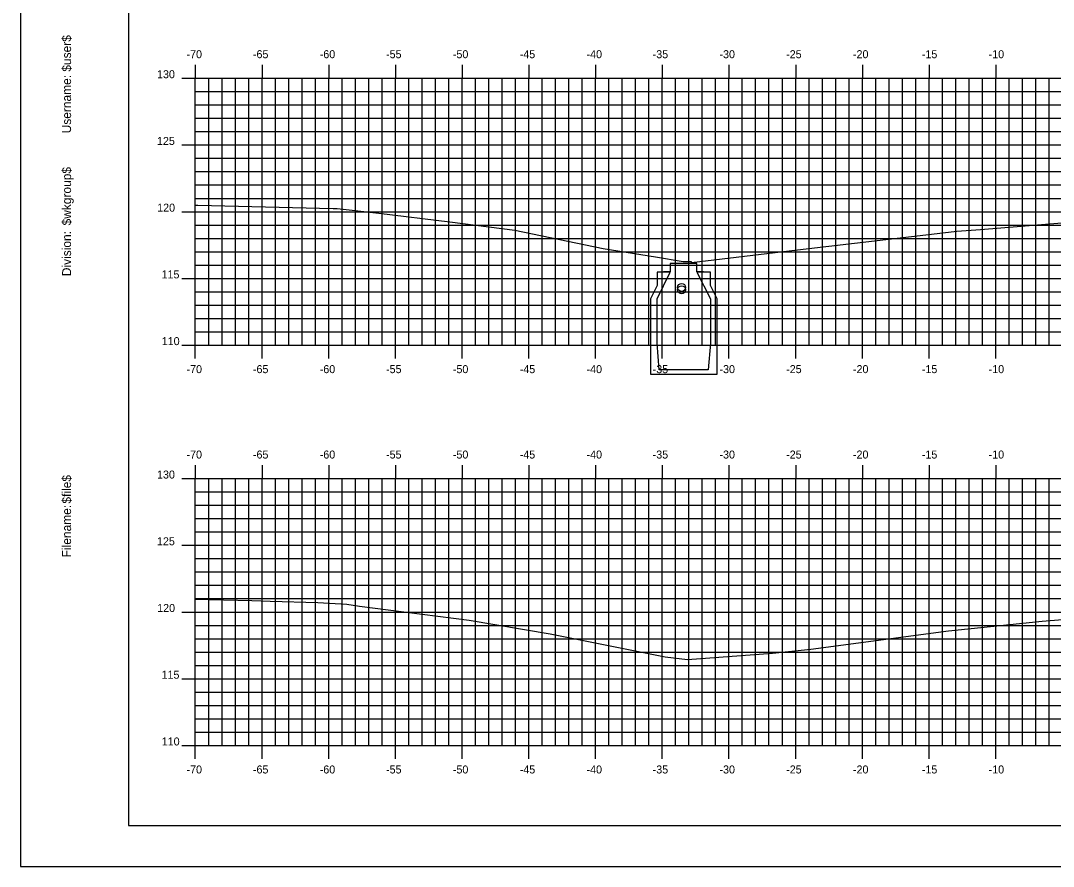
# Model space of a CAD drawing. Extents: x 853069 to 853241, y 365624 to 365734.
# Drawn here: x 853069 to 853146.4, y 365624 to 365687.3 of the extents above; entities that cross this region are included whole.
import ezdxf

# ---------------------------------------------------------------- set-up
doc = ezdxf.new("R2010")
doc.units = 0
for name, color, linetype in [('BORDER', 7, 'Continuous'), ('H_V ANNOTATION', 7, 'Continuous'), ('MAJOR', 7, 'Continuous'), ('MINOR', 7, 'Continuous'), ('PLOT BOUNDARY', 7, 'Continuous'), ('S_Drainage_CB', 7, 'Continuous'), ('S_Drainage_Invert', 7, 'Continuous'), ('S_Roadway_Centerline', 7, 'Continuous')]:
    doc.layers.add(name, color=color, linetype=linetype)

msp = doc.modelspace()

# ---------------------------------------------------------------- linework, layer by layer
at = {"layer": 'BORDER'}
msp.add_lwpolyline([(853077.062, 365627.027), (853237.062, 365627.027), (853237.062, 365732.027), (853077.062, 365732.027)], close=True, dxfattribs=at)
at = {"layer": 'MAJOR'}
for p, q in [((853082.061, 365684.029), (853082.061, 365683.027)), ((853087.061, 365684.029), (853087.061, 365683.027)), ((853092.061, 365684.029), (853092.061, 365683.027)), ((853097.061, 365684.029), (853097.061, 365683.027)), ((853102.061, 365684.029), (853102.061, 365683.027)), ((853107.061, 365684.029), (853107.061, 365683.027)), ((853112.061, 365684.029), (853112.061, 365683.027)), ((853117.061, 365684.029), (853117.061, 365683.027)), ((853122.061, 365684.029), (853122.061, 365683.027)), ((853127.061, 365684.029), (853127.061, 365683.027)), ((853132.061, 365684.029), (853132.061, 365683.027)), ((853137.061, 365684.029), (853137.061, 365683.027)), ((853142.061, 365684.029), (853142.061, 365683.027)), ((853081.059, 365683.027), (853082.061, 365683.027)), ((853082.061, 365683.027), (853222.061, 365683.027)), ((853082.061, 365663.027), (853082.061, 365683.027)), ((853082.061, 365663.027), (853082.061, 365683.027)), ((853082.061, 365683.027), (853222.061, 365683.027)), ((853087.061, 365663.027), (853087.061, 365683.027)), ((853092.061, 365663.027), (853092.061, 365683.027)), ((853097.061, 365663.027), (853097.061, 365683.027)), ((853102.061, 365663.027), (853102.061, 365683.027)), ((853107.061, 365663.027), (853107.061, 365683.027)), ((853112.061, 365663.027), (853112.061, 365683.027)), ((853117.061, 365663.027), (853117.061, 365683.027)), ((853122.061, 365663.027), (853122.061, 365683.027)), ((853127.061, 365663.027), (853127.061, 365683.027)), ((853132.061, 365663.027), (853132.061, 365683.027)), ((853137.061, 365663.027), (853137.061, 365683.027)), ((853142.061, 365663.027), (853142.061, 365683.027)), ((853081.059, 365678.027), (853082.061, 365678.027)), ((853082.061, 365678.027), (853222.061, 365678.027)), ((853081.059, 365673.027), (853082.061, 365673.027)), ((853082.061, 365673.027), (853222.061, 365673.027)), ((853081.059, 365668.027), (853082.061, 365668.027)), ((853082.061, 365668.027), (853222.061, 365668.027)), ((853081.059, 365663.027), (853082.061, 365663.027)), ((853082.061, 365663.027), (853222.061, 365663.027)), ((853082.061, 365663.027), (853222.061, 365663.027)), ((853082.061, 365662.025), (853082.061, 365663.027)), ((853087.061, 365662.025), (853087.061, 365663.027)), ((853092.061, 365662.025), (853092.061, 365663.027)), ((853097.061, 365662.025), (853097.061, 365663.027)), ((853102.061, 365662.025), (853102.061, 365663.027)), ((853107.061, 365662.025), (853107.061, 365663.027)), ((853112.061, 365662.025), (853112.061, 365663.027)), ((853117.061, 365662.025), (853117.061, 365663.027)), ((853122.061, 365662.025), (853122.061, 365663.027)), ((853127.061, 365662.025), (853127.061, 365663.027)), ((853132.061, 365662.025), (853132.061, 365663.027)), ((853137.061, 365662.025), (853137.061, 365663.027)), ((853142.061, 365662.025), (853142.061, 365663.027)), ((853082.061, 365654.029), (853082.061, 365653.027)), ((853087.061, 365654.029), (853087.061, 365653.027)), ((853092.061, 365654.029), (853092.061, 365653.027)), ((853097.061, 365654.029), (853097.061, 365653.027)), ((853102.061, 365654.029), (853102.061, 365653.027)), ((853107.061, 365654.029), (853107.061, 365653.027)), ((853112.061, 365654.029), (853112.061, 365653.027)), ((853117.061, 365654.029), (853117.061, 365653.027)), ((853122.061, 365654.029), (853122.061, 365653.027)), ((853127.061, 365654.029), (853127.061, 365653.027)), ((853132.061, 365654.029), (853132.061, 365653.027)), ((853137.061, 365654.029), (853137.061, 365653.027)), ((853142.061, 365654.029), (853142.061, 365653.027)), ((853081.059, 365653.027), (853082.061, 365653.027)), ((853082.061, 365653.027), (853222.061, 365653.027)), ((853082.061, 365633.027), (853082.061, 365653.027)), ((853082.061, 365633.027), (853082.061, 365653.027)), ((853082.061, 365653.027), (853222.061, 365653.027)), ((853087.061, 365633.027), (853087.061, 365653.027)), ((853092.061, 365633.027), (853092.061, 365653.027)), ((853097.061, 365633.027), (853097.061, 365653.027)), ((853102.061, 365633.027), (853102.061, 365653.027)), ((853107.061, 365633.027), (853107.061, 365653.027)), ((853112.061, 365633.027), (853112.061, 365653.027)), ((853117.061, 365633.027), (853117.061, 365653.027)), ((853122.061, 365633.027), (853122.061, 365653.027)), ((853127.061, 365633.027), (853127.061, 365653.027)), ((853132.061, 365633.027), (853132.061, 365653.027)), ((853137.061, 365633.027), (853137.061, 365653.027)), ((853142.061, 365633.027), (853142.061, 365653.027)), ((853081.059, 365648.027), (853082.061, 365648.027)), ((853082.061, 365648.027), (853222.061, 365648.027)), ((853081.059, 365643.027), (853082.061, 365643.027)), ((853082.061, 365643.027), (853222.061, 365643.027)), ((853081.059, 365638.027), (853082.061, 365638.027)), ((853082.061, 365638.027), (853222.061, 365638.027)), ((853081.059, 365633.027), (853082.061, 365633.027)), ((853082.061, 365633.027), (853222.061, 365633.027)), ((853082.061, 365633.027), (853222.061, 365633.027)), ((853082.061, 365632.025), (853082.061, 365633.027)), ((853087.061, 365632.025), (853087.061, 365633.027)), ((853092.061, 365632.025), (853092.061, 365633.027)), ((853097.061, 365632.025), (853097.061, 365633.027)), ((853102.061, 365632.025), (853102.061, 365633.027)), ((853107.061, 365632.025), (853107.061, 365633.027)), ((853112.061, 365632.025), (853112.061, 365633.027)), ((853117.061, 365632.025), (853117.061, 365633.027)), ((853122.061, 365632.025), (853122.061, 365633.027)), ((853127.061, 365632.025), (853127.061, 365633.027)), ((853132.061, 365632.025), (853132.061, 365633.027)), ((853137.061, 365632.025), (853137.061, 365633.027)), ((853142.061, 365632.025), (853142.061, 365633.027))]:
    msp.add_line(p, q, dxfattribs=at)
at = {"layer": 'MINOR'}
for p, q in [((853083.061, 365663.027), (853083.061, 365683.027)), ((853084.061, 365663.027), (853084.061, 365683.027)), ((853085.061, 365663.027), (853085.061, 365683.027)), ((853086.061, 365663.027), (853086.061, 365683.027)), ((853088.061, 365663.027), (853088.061, 365683.027)), ((853089.061, 365663.027), (853089.061, 365683.027)), ((853090.061, 365663.027), (853090.061, 365683.027)), ((853091.061, 365663.027), (853091.061, 365683.027)), ((853093.061, 365663.027), (853093.061, 365683.027)), ((853094.061, 365663.027), (853094.061, 365683.027)), ((853095.061, 365663.027), (853095.061, 365683.027)), ((853096.061, 365663.027), (853096.061, 365683.027)), ((853098.061, 365663.027), (853098.061, 365683.027)), ((853099.061, 365663.027), (853099.061, 365683.027)), ((853100.061, 365663.027), (853100.061, 365683.027)), ((853101.061, 365663.027), (853101.061, 365683.027)), ((853103.061, 365663.027), (853103.061, 365683.027)), ((853104.061, 365663.027), (853104.061, 365683.027)), ((853105.061, 365663.027), (853105.061, 365683.027)), ((853106.061, 365663.027), (853106.061, 365683.027)), ((853108.061, 365663.027), (853108.061, 365683.027)), ((853109.061, 365663.027), (853109.061, 365683.027)), ((853110.061, 365663.027), (853110.061, 365683.027)), ((853111.061, 365663.027), (853111.061, 365683.027)), ((853113.061, 365663.027), (853113.061, 365683.027)), ((853114.061, 365663.027), (853114.061, 365683.027)), ((853115.061, 365663.027), (853115.061, 365683.027)), ((853116.061, 365663.027), (853116.061, 365683.027)), ((853118.061, 365663.027), (853118.061, 365683.027)), ((853119.061, 365663.027), (853119.061, 365683.027)), ((853120.061, 365663.027), (853120.061, 365683.027)), ((853121.061, 365663.027), (853121.061, 365683.027)), ((853123.061, 365663.027), (853123.061, 365683.027)), ((853124.061, 365663.027), (853124.061, 365683.027)), ((853125.061, 365663.027), (853125.061, 365683.027)), ((853126.061, 365663.027), (853126.061, 365683.027)), ((853128.061, 365663.027), (853128.061, 365683.027)), ((853129.061, 365663.027), (853129.061, 365683.027)), ((853130.061, 365663.027), (853130.061, 365683.027)), ((853131.061, 365663.027), (853131.061, 365683.027)), ((853133.061, 365663.027), (853133.061, 365683.027)), ((853134.061, 365663.027), (853134.061, 365683.027)), ((853135.061, 365663.027), (853135.061, 365683.027)), ((853136.061, 365663.027), (853136.061, 365683.027)), ((853138.061, 365663.027), (853138.061, 365683.027)), ((853139.061, 365663.027), (853139.061, 365683.027)), ((853140.061, 365663.027), (853140.061, 365683.027)), ((853141.061, 365663.027), (853141.061, 365683.027)), ((853143.061, 365663.027), (853143.061, 365683.027)), ((853144.061, 365663.027), (853144.061, 365683.027)), ((853145.061, 365663.027), (853145.061, 365683.027)), ((853146.061, 365663.027), (853146.061, 365683.027)), ((853082.061, 365682.027), (853222.061, 365682.027)), ((853082.061, 365682.027), (853083.063, 365682.027)), ((853082.061, 365681.027), (853222.061, 365681.027)), ((853082.061, 365681.027), (853083.063, 365681.027)), ((853082.061, 365680.027), (853222.061, 365680.027)), ((853082.061, 365680.027), (853083.063, 365680.027)), ((853082.061, 365679.027), (853222.061, 365679.027)), ((853082.061, 365679.027), (853083.063, 365679.027)), ((853082.061, 365677.027), (853222.061, 365677.027)), ((853082.061, 365677.027), (853083.063, 365677.027)), ((853082.061, 365676.027), (853222.061, 365676.027)), ((853082.061, 365676.027), (853083.063, 365676.027)), ((853082.061, 365675.027), (853222.061, 365675.027)), ((853082.061, 365675.027), (853083.063, 365675.027)), ((853082.061, 365674.027), (853222.061, 365674.027)), ((853082.061, 365674.027), (853083.063, 365674.027)), ((853082.061, 365672.027), (853222.061, 365672.027)), ((853082.061, 365672.027), (853083.063, 365672.027)), ((853082.061, 365671.027), (853222.061, 365671.027)), ((853082.061, 365671.027), (853083.063, 365671.027)), ((853082.061, 365670.027), (853222.061, 365670.027)), ((853082.061, 365670.027), (853083.063, 365670.027)), ((853082.061, 365669.027), (853222.061, 365669.027)), ((853082.061, 365669.027), (853083.063, 365669.027)), ((853082.061, 365667.027), (853222.061, 365667.027)), ((853082.061, 365667.027), (853083.063, 365667.027)), ((853082.061, 365666.027), (853222.061, 365666.027)), ((853082.061, 365666.027), (853083.063, 365666.027)), ((853082.061, 365665.027), (853222.061, 365665.027)), ((853082.061, 365665.027), (853083.063, 365665.027)), ((853082.061, 365664.027), (853222.061, 365664.027)), ((853082.061, 365664.027), (853083.063, 365664.027)), ((853083.061, 365633.027), (853083.061, 365653.027)), ((853084.061, 365633.027), (853084.061, 365653.027)), ((853085.061, 365633.027), (853085.061, 365653.027)), ((853086.061, 365633.027), (853086.061, 365653.027)), ((853088.061, 365633.027), (853088.061, 365653.027)), ((853089.061, 365633.027), (853089.061, 365653.027)), ((853090.061, 365633.027), (853090.061, 365653.027)), ((853091.061, 365633.027), (853091.061, 365653.027)), ((853093.061, 365633.027), (853093.061, 365653.027)), ((853094.061, 365633.027), (853094.061, 365653.027)), ((853095.061, 365633.027), (853095.061, 365653.027)), ((853096.061, 365633.027), (853096.061, 365653.027)), ((853098.061, 365633.027), (853098.061, 365653.027)), ((853099.061, 365633.027), (853099.061, 365653.027)), ((853100.061, 365633.027), (853100.061, 365653.027)), ((853101.061, 365633.027), (853101.061, 365653.027)), ((853103.061, 365633.027), (853103.061, 365653.027)), ((853104.061, 365633.027), (853104.061, 365653.027)), ((853105.061, 365633.027), (853105.061, 365653.027)), ((853106.061, 365633.027), (853106.061, 365653.027)), ((853108.061, 365633.027), (853108.061, 365653.027)), ((853109.061, 365633.027), (853109.061, 365653.027)), ((853110.061, 365633.027), (853110.061, 365653.027)), ((853111.061, 365633.027), (853111.061, 365653.027)), ((853113.061, 365633.027), (853113.061, 365653.027)), ((853114.061, 365633.027), (853114.061, 365653.027)), ((853115.061, 365633.027), (853115.061, 365653.027)), ((853116.061, 365633.027), (853116.061, 365653.027)), ((853118.061, 365633.027), (853118.061, 365653.027)), ((853119.061, 365633.027), (853119.061, 365653.027)), ((853120.061, 365633.027), (853120.061, 365653.027)), ((853121.061, 365633.027), (853121.061, 365653.027)), ((853123.061, 365633.027), (853123.061, 365653.027)), ((853124.061, 365633.027), (853124.061, 365653.027)), ((853125.061, 365633.027), (853125.061, 365653.027)), ((853126.061, 365633.027), (853126.061, 365653.027)), ((853128.061, 365633.027), (853128.061, 365653.027)), ((853129.061, 365633.027), (853129.061, 365653.027)), ((853130.061, 365633.027), (853130.061, 365653.027)), ((853131.061, 365633.027), (853131.061, 365653.027)), ((853133.061, 365633.027), (853133.061, 365653.027)), ((853134.061, 365633.027), (853134.061, 365653.027)), ((853135.061, 365633.027), (853135.061, 365653.027)), ((853136.061, 365633.027), (853136.061, 365653.027)), ((853138.061, 365633.027), (853138.061, 365653.027)), ((853139.061, 365633.027), (853139.061, 365653.027)), ((853140.061, 365633.027), (853140.061, 365653.027)), ((853141.061, 365633.027), (853141.061, 365653.027)), ((853143.061, 365633.027), (853143.061, 365653.027)), ((853144.061, 365633.027), (853144.061, 365653.027)), ((853145.061, 365633.027), (853145.061, 365653.027)), ((853146.061, 365633.027), (853146.061, 365653.027)), ((853082.061, 365652.027), (853222.061, 365652.027)), ((853082.061, 365652.027), (853083.063, 365652.027)), ((853082.061, 365651.027), (853222.061, 365651.027)), ((853082.061, 365651.027), (853083.063, 365651.027)), ((853082.061, 365650.027), (853222.061, 365650.027)), ((853082.061, 365650.027), (853083.063, 365650.027)), ((853082.061, 365649.027), (853222.061, 365649.027)), ((853082.061, 365649.027), (853083.063, 365649.027)), ((853082.061, 365647.027), (853222.061, 365647.027)), ((853082.061, 365647.027), (853083.063, 365647.027)), ((853082.061, 365646.027), (853222.061, 365646.027)), ((853082.061, 365646.027), (853083.063, 365646.027)), ((853082.061, 365645.027), (853222.061, 365645.027)), ((853082.061, 365645.027), (853083.063, 365645.027)), ((853082.061, 365644.027), (853222.061, 365644.027)), ((853082.061, 365644.027), (853083.063, 365644.027)), ((853082.061, 365642.027), (853222.061, 365642.027)), ((853082.061, 365642.027), (853083.063, 365642.027)), ((853082.061, 365641.027), (853222.061, 365641.027)), ((853082.061, 365641.027), (853083.063, 365641.027)), ((853082.061, 365640.027), (853222.061, 365640.027)), ((853082.061, 365640.027), (853083.063, 365640.027)), ((853082.061, 365639.027), (853222.061, 365639.027)), ((853082.061, 365639.027), (853083.063, 365639.027)), ((853082.061, 365637.027), (853222.061, 365637.027)), ((853082.061, 365637.027), (853083.063, 365637.027)), ((853082.061, 365636.027), (853222.061, 365636.027)), ((853082.061, 365636.027), (853083.063, 365636.027)), ((853082.061, 365635.027), (853222.061, 365635.027)), ((853082.061, 365635.027), (853083.063, 365635.027)), ((853082.061, 365634.027), (853222.061, 365634.027)), ((853082.061, 365634.027), (853083.063, 365634.027))]:
    msp.add_line(p, q, dxfattribs=at)
at = {"layer": 'PLOT BOUNDARY'}
msp.add_lwpolyline([(853068.968, 365623.968), (853238.968, 365623.968), (853238.968, 365733.968), (853068.968, 365733.968)], close=True, dxfattribs=at)
at = {"layer": 'S_Drainage_CB'}
for p, q in [((853117.653, 365668.486), (853116.669, 365668.486)), ((853116.669, 365668.486), (853116.669, 365667.502)), ((853116.669, 365666.485), (853117.653, 365668.486)), ((853120.671, 365668.486), (853119.654, 365668.486)), ((853119.654, 365668.486), (853120.671, 365666.485)), ((853120.671, 365667.502), (853120.671, 365668.486)), ((853116.669, 365667.502), (853116.177, 365666.485)), ((853121.164, 365666.485), (853120.671, 365667.502)), ((853116.177, 365666.485), (853116.177, 365660.842)), ((853116.669, 365663.171), (853116.669, 365666.485)), ((853120.671, 365666.485), (853120.671, 365663.171)), ((853121.164, 365660.842), (853121.164, 365666.485)), ((853116.833, 365661.17), (853116.669, 365663.171)), ((853120.671, 365663.171), (853120.507, 365661.17)), ((853120.507, 365661.17), (853116.833, 365661.17)), ((853116.177, 365660.842), (853121.164, 365660.842))]:
    msp.add_line(p, q, dxfattribs=at)
msp.add_lwpolyline([(853120.146, 365668.528), (853119.654, 365668.528), (853119.654, 365669.151), (853117.653, 365669.151), (853117.653, 365668.528), (853117.161, 365668.528)], dxfattribs=at)
at = {"layer": 'S_Drainage_Invert'}
for centre in [(853118.507, 365667.174), (853118.508, 365667.348)]:
    msp.add_circle(centre, 0.3, dxfattribs=at)
at = {"layer": 'S_Roadway_Centerline'}
for points in [[(853082.061, 365673.526), (853082.245, 365673.521), (853092.387, 365673.271), (853092.705, 365673.256), (853095.804, 365672.904), (853101.129, 365672.27), (853106.019, 365671.634), (853112.642, 365670.277), (853116.549, 365669.631), (853118.622, 365669.292), (853119.205, 365669.303), (853119.25, 365669.221), (853127.2, 365670.16), (853138.083, 365671.448), (853139.145, 365671.579), (853140.919, 365671.697), (853160.13, 365673.253)], [(853082.061, 365643.991), (853086.291, 365643.882), (853087.669, 365643.84), (853091.243, 365643.737), (853093.424, 365643.609), (853094.36, 365643.47), (853102.585, 365642.422), (853108.657, 365641.392), (853117.274, 365639.664), (853118.943, 365639.457), (853125.323, 365639.934), (853128.209, 365640.25), (853138.507, 365641.623), (853145.525, 365642.331), (853150.736, 365642.756)]]:
    msp.add_lwpolyline(points, dxfattribs=at)

# ---------------------------------------------------------------- texts
at = {"layer": 'BORDER'}
for s, p in [('$user$', (853072.747, 365683.518)), ('Username:', (853072.747, 365678.895)), ('$wkgroup$', (853072.747, 365671.996)), ('Division:', (853072.747, 365668.193)), ('$file$', (853072.747, 365651.152)), ('Filename:', (853072.747, 365647.125))]:
    msp.add_text(s, height=0.6696, rotation=90, dxfattribs=at).set_placement(p)
at = {"layer": 'H_V ANNOTATION'}
for s, p in [('-70', (853081.403, 365684.527)), ('-65', (853086.379, 365684.527)), ('-60', (853091.387, 365684.527)), ('-55', (853096.358, 365684.527)), ('-50', (853101.366, 365684.527)), ('-45', (853106.379, 365684.527)), ('-40', (853111.387, 365684.527)), ('-35', (853116.342, 365684.527)), ('-30', (853121.35, 365684.527)), ('-25', (853126.347, 365684.527)), ('-20', (853131.355, 365684.527)), ('-15', (853136.518, 365684.527)), ('-10', (853141.526, 365684.527)), ('130', (853079.191, 365683.027)), ('125', (853079.186, 365678.027)), ('120', (853079.202, 365673.027)), ('115', (853079.529, 365668.027)), ('110', (853079.545, 365663.027)), ('-70', (853081.403, 365660.927)), ('-65', (853086.379, 365660.927)), ('-60', (853091.387, 365660.927)), ('-55', (853096.358, 365660.927)), ('-50', (853101.366, 365660.927)), ('-45', (853106.379, 365660.927)), ('-40', (853111.387, 365660.927)), ('-35', (853116.342, 365660.927)), ('-30', (853121.35, 365660.927)), ('-25', (853126.347, 365660.927)), ('-20', (853131.355, 365660.927)), ('-15', (853136.518, 365660.927)), ('-10', (853141.526, 365660.927)), ('-70', (853081.403, 365654.527)), ('-65', (853086.379, 365654.527)), ('-60', (853091.387, 365654.527)), ('-55', (853096.358, 365654.527)), ('-50', (853101.366, 365654.527)), ('-45', (853106.379, 365654.527)), ('-40', (853111.387, 365654.527)), ('-35', (853116.342, 365654.527)), ('-30', (853121.35, 365654.527)), ('-25', (853126.347, 365654.527)), ('-20', (853131.355, 365654.527)), ('-15', (853136.518, 365654.527)), ('-10', (853141.526, 365654.527)), ('130', (853079.191, 365653.027)), ('125', (853079.186, 365648.027)), ('120', (853079.202, 365643.027)), ('115', (853079.529, 365638.027)), ('110', (853079.545, 365633.027)), ('-70', (853081.403, 365630.927)), ('-65', (853086.379, 365630.927)), ('-60', (853091.387, 365630.927)), ('-55', (853096.358, 365630.927)), ('-50', (853101.366, 365630.927)), ('-45', (853106.379, 365630.927)), ('-40', (853111.387, 365630.927)), ('-35', (853116.342, 365630.927)), ('-30', (853121.35, 365630.927)), ('-25', (853126.347, 365630.927)), ('-20', (853131.355, 365630.927)), ('-15', (853136.518, 365630.927)), ('-10', (853141.526, 365630.927))]:
    msp.add_text(s, height=0.6, dxfattribs=at).set_placement(p)
at = {"layer": 'MAJOR'}
for p in [(853082.057, 365663.027), (853082.057, 365633.027)]:
    msp.add_text('-', height=0.006, dxfattribs=at).set_placement(p)

doc.saveas('drawing.dxf')
